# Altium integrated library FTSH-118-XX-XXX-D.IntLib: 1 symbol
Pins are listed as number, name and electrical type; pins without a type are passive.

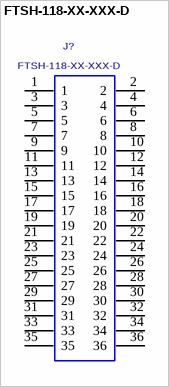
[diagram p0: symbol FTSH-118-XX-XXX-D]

## FTSH-118-XX-XXX-D
designator J?
TERMINAL STRIP, .050"(1.27mm) PITCH, 36 PINS.; MANUFACTURER: SAMTEC
footprint FTSH-118-XX-XXX-D
pins: 1, 2, 3, 4, 5, 6, 7, 8, 9, 10, 11, 12, 13, 14, 15, 16, 17, 18, 19, 20, 21, 22, 23, 24, 25, 26, 27, 28, 29, 30, 31, 32, 33, 34, 35, 36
